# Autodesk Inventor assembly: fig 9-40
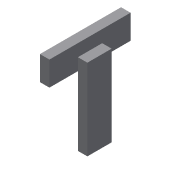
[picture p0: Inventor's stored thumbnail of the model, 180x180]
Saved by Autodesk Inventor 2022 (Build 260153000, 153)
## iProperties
Created: 2013-07
Part Number: fig 9-40
Document SubType Name: Assembly
Designer: CADCIM
Author: CADCIM
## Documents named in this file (2)
- D:\PROJECTS_2021\Resources\Part Files\c09_Inv_2022_prt\fig 9-41.iam
- D:\PROJECTS_2021\Resources\Part Files\c09_Inv_2022_prt\12.ipt
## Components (2 placed, 1 different names)
1. 12:1 — Rigid:1
2. 12:2 — Rigid:1
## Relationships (1: WeldJoint 1)
- Rigid:1 [WeldJoint]: 12:1 ↔ 12:2
